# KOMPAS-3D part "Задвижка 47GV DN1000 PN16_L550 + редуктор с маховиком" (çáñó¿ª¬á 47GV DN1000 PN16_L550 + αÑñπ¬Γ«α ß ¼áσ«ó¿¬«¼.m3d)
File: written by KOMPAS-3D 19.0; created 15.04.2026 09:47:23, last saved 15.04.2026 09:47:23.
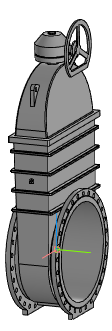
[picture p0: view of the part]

Document properties: Автор: Энергия; Полное имя файла: ..\..\Задвижка 47GV DN1000 PN16_L550 + редуктор с маховиком.a3d

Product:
- Part/product: Задвижка 47GV DN1000 PN16_L550 + редуктор с маховиком
    Масса: 5173.68

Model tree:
1. Операция без истории:1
